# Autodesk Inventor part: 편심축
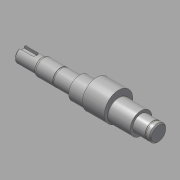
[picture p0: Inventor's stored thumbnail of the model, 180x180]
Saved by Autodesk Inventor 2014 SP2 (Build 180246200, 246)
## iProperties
Created: 2015-12
Part Number: 편심축
Material: 강철, 연강
Document SubType Name: Modeling
Designer: mduedu
Density: 7.86 g/cm^3
Appearance: 강철
Author: mduedu
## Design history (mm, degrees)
sketch "스케치1"
  geometry: L1 (-62.5, 0)-(62.5, 0); L2 (-62.5, 0)-(-62.5, 6.5); L3 (-62.5, 6.5)-(-43.5, 6.5); L4 (-43.5, 7)-(-42.634, 7.5); L5 (-42.634, 7.5)-(-9.5, 7.5); L6 (-9.5, 7.5)-(-9.5, 10); L7 (-9.5, 10)-(46.5, 10); L8 (46.5, 10)-(46.5, 7.5); L9 (46.5, 7.5)-(62.5, 7.5); L10 (62.5, 7.5)-(62.5, 0); L11 (-43.5, 6.5)-(-43.5, 7); 2 further points
  constraints: 22 end point, 6 parallel, 2 perpendicular, 1 coincident, 1 horizontal, 1 midpoint, 1 vertical
  dimensions: "d0" = 13 diameter of L3 L1; "d2" = 15 diameter of L5 L1; "d3" = 20 diameter of L7 L1; "d5" = 15 diameter of L9 L1; "d6" = 125 distance of L1.start L1.end; "d7" = 19 distance of L2.end L3.end; "d8" = 34 distance from line of L6 L3.end; "d9" = 56 distance of L6.end L7.end; "d41" = 14 diameter of L4.start L1; "d42" = 30 deg angle of L4 L3
revolve "회전1" sketch "스케치1" stored, may be unused: angle "d11" = 90 deg
node "작업 평면1"
sketch "스케치2"
  geometry: C1 r 13 at (0, 3); 1 further point
  constraints: 1 centre point, 1 vertical alignment
  dimensions: "d13" = 26 diameter of C1; "d14" = 3 distance of point (0, 0) C1.centre
extrude "돌출1" join sketch "스케치2" distance "d15" = 20; taper "d16" = 0 deg
node "작업 평면2"
sketch "스케치3"
  geometry: L1 (9.5, -2.5)-(-2.5, -2.5); L2 (-2.5, 2.5)-(9.5, 2.5); L3 (9.5, 2.5)-(9.5, -2.5); L4 (9.5, 6.5)-(9.5, -6.5) reference; A1 r 2.5 centre (-2.5, 0) between (-2.5, 2.5) and (-2.5, -2.5); 1 further point
  constraints: 6 end point, 2 point on circle, 2 tangent, 1 centre point, 1 collinear, 1 horizontal, 1 horizontal alignment, 1 parallel
  dimensions: "d17" = 5 distance of L2.end L1.start; "d19" = 12 distance from line of A1.centre L3
extrude "돌출2" cut sketch "스케치3" distance "d20" = 3; taper "d21" = 0 deg
chamfer "모따기1" distance "d22" = 1; stored, may be unused: second distance "d23" = 2, angle "d24" = 45 deg
fillet "모깎기1" dims "d25" = 3
sketch "스케치4"
  geometry: L1 (-9.5, -10)-(-9.5, 10) reference; L2 (-9.5, 0)-(0, 0); L3 (-26.65, 12.15)-(-25.5, 12.15); L4 (-25.5, 12.15)-(-25.5, 7.15); L5 (-25.5, 7.15)-(-26.65, 7.15); L6 (-26.65, 7.15)-(-26.65, 12.15); L7 (57.5, 12.15)-(58.65, 12.15); L8 (58.65, 12.15)-(58.65, 7.15); L9 (58.65, 7.15)-(57.5, 7.15); L10 (57.5, 7.15)-(57.5, 12.15); L11 (62.5, -7.5)-(62.5, 7.5) reference
  constraints: 18 end point, 4 parallel, 2 horizontal, 2 perpendicular, 1 midpoint
  dimensions: "d26" = 16 distance between parallel lines of L4 L1; "d27" = 1.15 distance of L3.start L3.end; "d28" = 14.3 diameter of L5 L2; "d29" = 5 distance of L3.end L4.end; "d30" = 1.15 distance of L7.start L7.end; "d31" = 5 distance of L7.end L8.end; "d32" = 5 distance between parallel lines of L10 L11; "d33" = 14.3 diameter of L9 L2
revolve "회전2" sketch "스케치4" stored, may be unused: angle "d34" = 90 deg
chamfer "모따기2" distance "d35" = 1; stored, may be unused: second distance "d36" = 2, angle "d37" = 45 deg
fillet "모깎기2" dims "d38" = 0.3
sketch "스케치5"
  geometry: 2 further points
  constraints: 1 coincident
sketch "스케치6"
  geometry: 1 further point
hole "구멍1" sketch "스케치6" at (2.5, -3.5) diameter "d43" = 4.917; stored, may be unused: countersink angle "d47" = 90 deg, drill point angle "d49" = 120 deg; dims "d44" = 14, "d45" = 4, "d46" = 2, "d48" = 17
node "솔리드1"
other parameters: "d12" = -15.5
